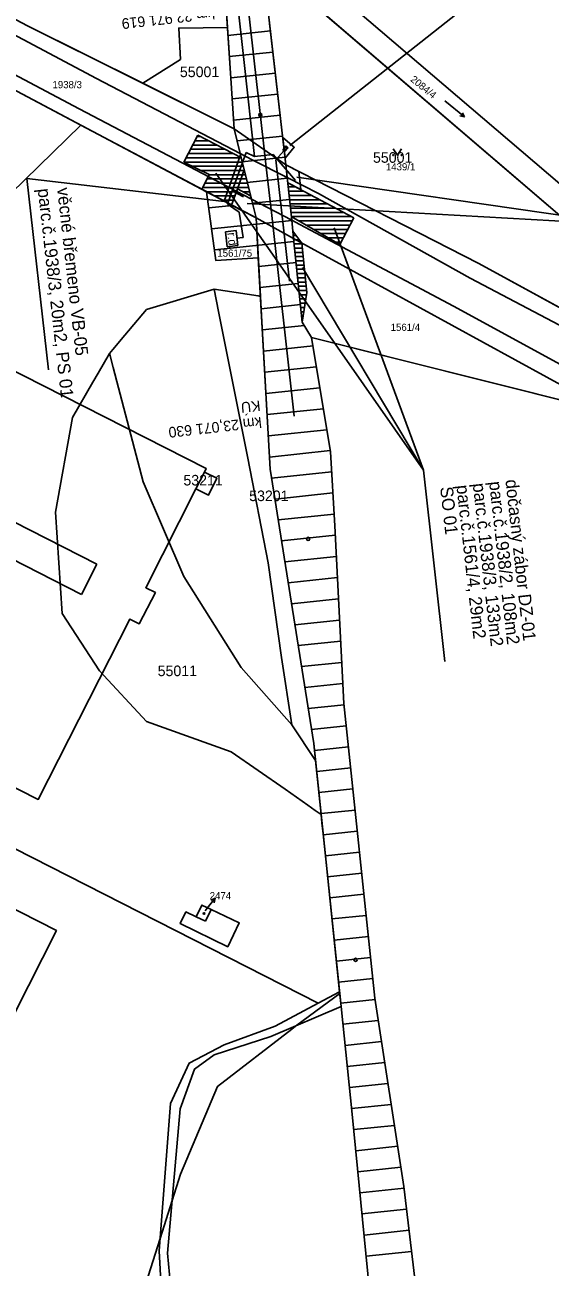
# Model space of a CAD drawing. Extents: x -794765 to -785424, y -1118958 to -1108731.
# Drawn here: x -792660.4 to -792536.3, y -1110737.1 to -1110443.9 of the extents above; entities that cross this region are included whole.
import ezdxf

# ---------------------------------------------------------------- set-up
doc = ezdxf.new("R2010")
doc.units = 0
for name, color, linetype in [('Level 66', 7, 'Continuous'), ('Level 75', 7, 'Continuous'), ('Level 76', 7, 'Continuous'), ('Level 77', 7, 'Continuous'), ('Level 78', 7, 'Continuous'), ('Level 79', 7, 'Continuous'), ('Level 80', 7, 'Continuous'), ('Level 81', 7, 'Continuous'), ('Vrstva 1', 7, 'Continuous'), ('Vrstva 53', 7, 'Continuous')]:
    doc.layers.add(name, color=color, linetype=linetype)

msp = doc.modelspace()

# ---------------------------------------------------------------- linework, layer by layer
at = {"layer": 'Level 66'}
for p, q in [((-792561.2, -1110461.83), (-792556.54, -1110465.6)), ((-792556.54, -1110465.6), (-792557.62, -1110465.38)), ((-792556.54, -1110465.6), (-792556.98, -1110464.6))]:
    msp.add_line(p, q, dxfattribs=at)
msp.add_lwpolyline([(-792573.4, -1110473.11), (-792572.4, -1110474.61), (-792571.4, -1110473.11)], dxfattribs=at)
for centre in [(-792573.4, -1110474.61), (-792571.4, -1110474.61)]:
    msp.add_circle(centre, 0.1, dxfattribs=at)
at = {"layer": 'Level 75'}
for p, q in [((-792605.76, -1110415.98), (-792598.74, -1110476.89)), ((-792609.51, -1110474.26), (-792610.94, -1110468.39)), ((-792606.89, -1110485.01), (-792609.51, -1110474.26)), ((-792598.74, -1110476.89), (-792598.42, -1110479.91)), ((-792598.42, -1110479.91), (-792597.37, -1110489.98)), ((-792617.47, -1110483.28), (-792605.8, -1110489.46)), ((-792605.8, -1110489.46), (-792606.89, -1110485.01)), ((-792605.8, -1110489.46), (-792605.27, -1110498.84)), ((-792605.8, -1110489.46), (-792596.92, -1110494.31)), ((-792597.37, -1110489.98), (-792596.92, -1110494.31)), ((-792521.65, -1110535.49), (-792596.92, -1110494.31)), ((-792592.65, -1110517.65), (-792521.65, -1110535.49)), ((-792717.66, -1110610.53), (-792591.1, -1110674.8)), ((-792586.07, -1110672.12), (-792591.1, -1110674.8)), ((-792585.71, -1110675.6), (-792586.07, -1110672.12))]:
    msp.add_line(p, q, dxfattribs=at)
for points in [[(-792861.96, -1110336.71), (-792834.85, -1110346.23), (-792831.02, -1110348.4), (-792787.15, -1110373.19), (-792780.58, -1110380.1), (-792659.8, -1110444.12), (-792610.94, -1110468.39)], [(-792606.36, -1110410.71), (-792601.62, -1110412.42), (-792591.51, -1110432.33), (-792497.5, -1110512.53), (-792447.39, -1110553.73)], [(-792610.94, -1110468.39), (-792611.85, -1110455.28), (-792614.37, -1110416.71), (-792614.4, -1110416.41)], [(-792451.16, -1110559.06), (-792501.08, -1110517.07), (-792597.68, -1110434.36), (-792604.19, -1110416.91), (-792605.76, -1110415.98)], [(-792617.47, -1110483.28), (-792667.41, -1110456.84), (-792670.27, -1110455.33)], [(-792598.74, -1110476.89), (-792553.17, -1110500.22), (-792498.93, -1110529.8)], [(-792605.27, -1110498.84), (-792615.26, -1110499.53), (-792617.47, -1110483.28)], [(-792596.92, -1110494.31), (-792594.86, -1110514.07), (-792592.65, -1110517.65)], [(-792605.27, -1110498.84), (-792602.43, -1110548.75), (-792592.15, -1110613.52), (-792589.48, -1110639.3), (-792589.16, -1110642.36), (-792586.07, -1110672.12)], [(-792721.79, -1110511.93), (-792715.49, -1110515.15), (-792708.94, -1110502.27), (-792617.55, -1110548.61), (-792617.98, -1110549.46), (-792615.07, -1110550.92), (-792617.03, -1110554.92), (-792619.99, -1110553.41), (-792631.85, -1110576.75), (-792629.58, -1110577.89), (-792633.4, -1110585.25), (-792635.6, -1110584.14), (-792657.23, -1110626.73), (-792748.62, -1110580.29), (-792742.08, -1110567.4), (-792748.36, -1110564.21)], [(-792592.65, -1110517.65), (-792588.22, -1110544.64), (-792587.19, -1110562.1), (-792585.02, -1110604.07), (-792577.72, -1110673.66), (-792570.87, -1110718.09), (-792561.36, -1110798.02), (-792555.3, -1110868.45), (-792554.86, -1110872.76)], [(-792692.14, -1110649.21), (-792691.69, -1110649.43), (-792687.06, -1110640.34), (-792652.95, -1110657.7), (-792692.66, -1110735.91), (-792726.8, -1110718.56), (-792722.01, -1110709.13)], [(-792619.91, -1110654.4), (-792618.59, -1110651.65), (-792616.4, -1110652.69), (-792609.75, -1110655.86), (-792612.47, -1110661.5), (-792623.69, -1110656.05), (-792622.34, -1110653.28), (-792619.91, -1110654.4)], [(-792591.1, -1110674.8), (-792601.29, -1110680.22), (-792613.33, -1110684.67), (-792621.59, -1110688.96), (-792626.04, -1110698.47), (-792628.69, -1110733.25), (-792627.76, -1110750.6), (-792629.75, -1110793.66), (-792632.7, -1110825.48)], [(-792585.71, -1110675.6), (-792602.33, -1110682.67), (-792615.66, -1110686.98), (-792620.3, -1110690.38), (-792623.71, -1110699.73), (-792626.72, -1110733.83), (-792625.08, -1110751.48), (-792626.88, -1110794.12), (-792629.4, -1110816.41), (-792632.7, -1110825.48)], [(-792564.11, -1110874.31), (-792564.67, -1110869.51), (-792573.72, -1110796.5), (-792583.08, -1110701.05), (-792585.71, -1110675.6)]]:
    msp.add_lwpolyline(points, dxfattribs=at)
at = {"layer": 'Level 77'}
for p, q in [((-792643.45, -1110456.57), (-792675.45, -1110439.61)), ((-792678.77, -1110447.22), (-792647.57, -1110463.72)), ((-792643.45, -1110456.57), (-792609.51, -1110474.26)), ((-792647.57, -1110463.72), (-792608.66, -1110484.08)), ((-792598.74, -1110476.89), (-792610.94, -1110468.39)), ((-792606.67, -1110475.74), (-792609.51, -1110474.26)), ((-792606.67, -1110475.74), (-792598.42, -1110479.91)), ((-792591.02, -1110483.65), (-792598.42, -1110479.91)), ((-792608.66, -1110484.08), (-792606.89, -1110485.01)), ((-792606.89, -1110485.01), (-792597.37, -1110489.98)), ((-792555.17, -1110503.69), (-792591.02, -1110483.65)), ((-792595.45, -1110490.98), (-792597.37, -1110489.98)), ((-792595.45, -1110490.98), (-792559.11, -1110510.27)), ((-792527.76, -1110518.12), (-792555.17, -1110503.69)), ((-792559.11, -1110510.27), (-792531.29, -1110525.47)), ((-792723.33, -1110530.62), (-792643.41, -1110571.15)), ((-792726.95, -1110537.73), (-792647.05, -1110578.32)), ((-792619.99, -1110553.41), (-792617.98, -1110549.46)), ((-792643.41, -1110571.15), (-792647.05, -1110578.32)), ((-792616.4, -1110652.69), (-792617.71, -1110655.45)), ((-792617.71, -1110655.45), (-792619.91, -1110654.4))]:
    msp.add_line(p, q, dxfattribs=at)
at = {"layer": 'Level 78'}
for p, q in [((-792612.43, -1110446.37), (-792602.38, -1110445.31)), ((-792612.11, -1110451.36), (-792601.81, -1110450.28)), ((-792611.78, -1110456.35), (-792601.23, -1110455.25)), ((-792611.43, -1110461.35), (-792600.66, -1110460.21)), ((-792611.08, -1110466.34), (-792600.09, -1110465.18)), ((-792610.24, -1110471.28), (-792599.52, -1110470.15)), ((-792609.04, -1110476.18), (-792598.94, -1110475.12)), ((-792607.85, -1110481.08), (-792598.41, -1110480.09)), ((-792606.65, -1110485.98), (-792597.88, -1110485.06)), ((-792616.96, -1110487.06), (-792611.42, -1110486.48)), ((-792616.28, -1110492.02), (-792597.36, -1110490.03)), ((-792615.61, -1110496.98), (-792596.85, -1110495.01)), ((-792605.15, -1110500.91), (-792596.33, -1110499.98)), ((-792604.86, -1110505.9), (-792595.81, -1110504.95)), ((-792604.58, -1110510.9), (-792595.29, -1110509.92)), ((-792604.29, -1110515.9), (-792594.37, -1110514.86)), ((-792604.01, -1110520.9), (-792592.32, -1110519.67)), ((-792603.73, -1110525.89), (-792591.51, -1110524.61)), ((-792603.44, -1110530.89), (-792590.7, -1110529.55)), ((-792603.16, -1110535.89), (-792589.89, -1110534.49)), ((-792602.88, -1110540.89), (-792589.07, -1110539.44)), ((-792602.59, -1110545.89), (-792588.26, -1110544.38)), ((-792602.1, -1110550.86), (-792587.94, -1110549.37)), ((-792601.31, -1110555.81), (-792587.65, -1110554.37)), ((-792600.53, -1110560.75), (-792587.35, -1110559.37)), ((-792599.74, -1110565.7), (-792587.07, -1110564.36)), ((-792598.96, -1110570.64), (-792586.81, -1110569.36)), ((-792598.17, -1110575.59), (-792586.56, -1110574.36)), ((-792597.39, -1110580.53), (-792586.3, -1110579.37)), ((-792596.6, -1110585.48), (-792586.04, -1110584.37)), ((-792595.82, -1110590.42), (-792585.78, -1110589.37)), ((-792595.03, -1110595.37), (-792585.52, -1110594.37)), ((-792594.25, -1110600.31), (-792585.26, -1110599.37)), ((-792593.46, -1110605.26), (-792584.99, -1110604.37)), ((-792592.68, -1110610.2), (-792584.47, -1110609.34)), ((-792591.98, -1110615.16), (-792583.95, -1110614.31)), ((-792591.46, -1110620.13), (-792583.42, -1110619.28)), ((-792590.95, -1110625.1), (-792582.9, -1110624.26)), ((-792590.43, -1110630.08), (-792582.38, -1110629.23)), ((-792589.92, -1110635.05), (-792581.86, -1110634.2)), ((-792589.4, -1110640.02), (-792581.34, -1110639.17)), ((-792588.88, -1110645), (-792580.82, -1110644.15)), ((-792588.37, -1110649.97), (-792580.29, -1110649.12)), ((-792587.85, -1110654.94), (-792579.77, -1110654.09)), ((-792587.34, -1110659.92), (-792579.25, -1110659.07)), ((-792586.82, -1110664.89), (-792578.73, -1110664.04)), ((-792586.31, -1110669.86), (-792578.21, -1110669.01)), ((-792585.79, -1110674.84), (-792577.67, -1110673.98)), ((-792585.28, -1110679.81), (-792576.91, -1110678.93)), ((-792584.76, -1110684.78), (-792576.14, -1110683.88)), ((-792584.25, -1110689.76), (-792575.38, -1110688.82)), ((-792583.73, -1110694.73), (-792574.62, -1110693.77)), ((-792583.22, -1110699.7), (-792573.86, -1110698.72)), ((-792582.72, -1110704.68), (-792573.09, -1110703.67)), ((-792582.24, -1110709.65), (-792572.33, -1110708.61)), ((-792581.75, -1110714.63), (-792571.57, -1110713.56)), ((-792581.26, -1110719.61), (-792570.82, -1110718.51)), ((-792580.77, -1110724.58), (-792570.23, -1110723.48)), ((-792580.28, -1110729.56), (-792569.64, -1110728.44)), ((-792579.8, -1110734.54), (-792569.05, -1110733.41))]:
    msp.add_line(p, q, dxfattribs=at)
at = {"layer": 'Level 79'}
msp.add_circle((-792618.08, -1110653.65), 0.175, dxfattribs=at)
at = {"layer": 'Level 80'}
for p, q in [((-792617.31, -1110652.36), (-792615.42, -1110650.03)), ((-792615.42, -1110650.03), (-792616.44, -1110650.49)), ((-792615.42, -1110650.03), (-792615.66, -1110651.12)), ((-792617.84, -1110653), (-792617.31, -1110652.36))]:
    msp.add_line(p, q, dxfattribs=at)
at = {"layer": 'Level 81'}
for p, q in [((-792593.91, -1110437.59), (-792502.91, -1110515.5)), ((-792674.7, -1110494.31), (-792647.2, -1110467.54)), ((-792597.35, -1110609.14), (-792591.73, -1110617.57)), ((-792591.73, -1110617.57), (-792590.41, -1110630.32))]:
    msp.add_line(p, q, dxfattribs=at)
for points in [[(-792739.95, -1110324.15), (-792684.9, -1110369.28), (-792666.12, -1110385.5), (-792634.65, -1110411.27), (-792624.78, -1110416.77), (-792614.4, -1110416.41), (-792614.37, -1110416.71), (-792612.56, -1110444.48)], [(-792733.14, -1110405.24), (-792659.8, -1110444.12), (-792632.57, -1110457.65)], [(-792744.86, -1110416.1), (-792741.07, -1110418.09), (-792681.03, -1110449.67), (-792667.41, -1110456.84), (-792647.2, -1110467.54)], [(-792632.57, -1110457.65), (-792623.67, -1110452.04), (-792624.04, -1110444.63), (-792612.56, -1110444.48)], [(-792632.57, -1110457.65), (-792610.94, -1110468.39), (-792611.85, -1110455.28), (-792612.56, -1110444.48)], [(-792602.59, -1110443.51), (-792598.74, -1110476.89), (-792553.17, -1110500.22), (-792510.76, -1110523.35)], [(-792647.2, -1110467.54), (-792605.8, -1110489.46), (-792604.74, -1110508.01)], [(-792640.41, -1110521.42), (-792639.64, -1110520.51), (-792636.77, -1110517.11), (-792631.64, -1110511.05), (-792615.69, -1110506.27)], [(-792615.69, -1110506.27), (-792605.32, -1110507.86), (-792604.74, -1110508.01)], [(-792615.69, -1110506.27), (-792614.64, -1110511.53), (-792607.72, -1110546.14), (-792602.93, -1110570.87), (-792599.74, -1110593.19), (-792597.35, -1110609.14)], [(-792604.74, -1110508.01), (-792604.4, -1110513.99), (-792602.43, -1110548.75), (-792592.15, -1110613.52), (-792591.73, -1110617.57)], [(-792561.36, -1110798.02), (-792570.87, -1110718.09), (-792577.72, -1110673.66), (-792585.02, -1110604.07), (-792587.19, -1110562.1), (-792588.22, -1110544.64), (-792592.65, -1110517.65), (-792521.65, -1110535.49), (-792507.87, -1110543.93), (-792480.76, -1110589.07), (-792470.5, -1110600.97), (-792465.27, -1110607.03), (-792463.97, -1110608.54), (-792457.87, -1110610.45), (-792459.97, -1110623.35), (-792464.15, -1110640.29), (-792461.3, -1110649.15), (-792444.03, -1110661.2), (-792443.21, -1110662.17)], [(-792640.41, -1110521.42), (-792643.13, -1110526.12), (-792644.35, -1110528.22), (-792649.18, -1110536.57), (-792653.17, -1110558.9), (-792651.58, -1110582.83), (-792642.81, -1110596.38), (-792631.64, -1110608.35), (-792611.7, -1110615.52), (-792598.94, -1110624.3), (-792593.55, -1110628.1), (-792591.81, -1110629.33), (-792590.41, -1110630.32)], [(-792640.41, -1110521.42), (-792640.35, -1110521.65), (-792639.53, -1110524.79), (-792632.44, -1110551.73), (-792622.87, -1110574.06), (-792609.31, -1110595.59), (-792597.35, -1110609.14)], [(-792590.41, -1110630.32), (-792590.21, -1110632.23), (-792589.94, -1110634.82), (-792589.48, -1110639.3), (-792589.16, -1110642.36), (-792586.07, -1110672.12), (-792586.02, -1110672.57)], [(-792649.15, -1110846.82), (-792642.01, -1110836.43), (-792638.82, -1110814.1), (-792636.43, -1110779.01), (-792634.03, -1110747.91), (-792628.47, -1110730.36), (-792625.62, -1110721.38), (-792623.67, -1110715.21), (-792614.89, -1110694.48), (-792597.35, -1110680.92), (-792596.17, -1110680.05), (-792586.02, -1110672.57)], [(-792586.02, -1110672.57), (-792585.71, -1110675.6), (-792583.08, -1110701.05), (-792573.72, -1110796.5), (-792564.67, -1110869.51), (-792564.11, -1110874.31), (-792552.78, -1110972.03), (-792550.9, -1110987.8), (-792549.9, -1110996.2), (-792549.58, -1110998.89), (-792549, -1111003.82), (-792541.78, -1111065.45)]]:
    msp.add_lwpolyline(points, dxfattribs=at)
at = {"layer": 'Vrstva 1'}
for p, q in [((-792613.96, -1110405.45), (-792608.61, -1110452.76)), ((-792608.61, -1110452.76), (-792606.17, -1110474.95)), ((-792619.53, -1110469.94), (-792622.88, -1110476.25)), ((-792620.23, -1110471.25), (-792617, -1110471.25)), ((-792619.7, -1110470.25), (-792618.92, -1110470.25)), ((-792619.53, -1110469.94), (-792609.26, -1110475.29)), ((-792596.78, -1110472.75), (-792599.48, -1110470.49)), ((-792621.82, -1110474.25), (-792611.25, -1110474.25)), ((-792621.29, -1110473.25), (-792613.17, -1110473.25)), ((-792620.76, -1110472.25), (-792615.09, -1110472.25)), ((-792609.44, -1110474.53), (-792613.35, -1110485.46)), ((-792608.13, -1110474.01), (-792611.42, -1110483.05)), ((-792606.17, -1110474.95), (-792608.13, -1110474.01)), ((-792606.17, -1110474.95), (-792601.71, -1110474.49)), ((-792601.71, -1110474.49), (-792596.44, -1110480.58)), ((-792601.15, -1110475.7), (-792599.22, -1110473.58)), ((-792598.7, -1110472.45), (-792599.47, -1110473.37)), ((-792598.7, -1110472.45), (-792599.47, -1110473.37)), ((-792599.47, -1110473.37), (-792598.96, -1110473.79)), ((-792599.47, -1110473.37), (-792598.96, -1110473.79)), ((-792599.29, -1110472.15), (-792599.29, -1110472.15)), ((-792598.58, -1110472.54), (-792599.22, -1110473.31)), ((-792598.58, -1110472.54), (-792599.22, -1110473.31)), ((-792599.22, -1110473.31), (-792598.95, -1110473.54)), ((-792599.22, -1110473.31), (-792598.95, -1110473.54)), ((-792598.96, -1110473.79), (-792598.19, -1110472.87)), ((-792598.19, -1110472.87), (-792598.96, -1110473.79)), ((-792598.95, -1110473.54), (-792598.31, -1110472.78)), ((-792598.31, -1110472.78), (-792598.95, -1110473.54)), ((-792598.92, -1110475.3), (-792596.78, -1110472.75)), ((-792598.19, -1110472.87), (-792598.7, -1110472.45)), ((-792598.19, -1110472.87), (-792598.7, -1110472.45)), ((-792622.88, -1110476.25), (-792616.88, -1110479.22)), ((-792622.88, -1110476.25), (-792609.03, -1110476.25)), ((-792622.35, -1110475.25), (-792609.33, -1110475.25)), ((-792620.86, -1110477.25), (-792608.78, -1110477.25)), ((-792597.92, -1110504.39), (-792601.15, -1110475.7)), ((-792598.74, -1110476.89), (-792598.42, -1110479.91)), ((-792654.86, -1110525.34), (-792659.91, -1110480.13)), ((-792659.91, -1110480.13), (-792612.63, -1110485.66)), ((-792618.84, -1110478.25), (-792608.54, -1110478.25)), ((-792618.57, -1110482.7), (-792616.88, -1110479.22)), ((-792617.39, -1110480.25), (-792608.05, -1110480.25)), ((-792616.9, -1110479.25), (-792608.3, -1110479.25)), ((-792566.22, -1110549), (-792615.31, -1110478.87)), ((-792608.58, -1110478.06), (-792610.18, -1110482.54)), ((-792518.1, -1110491.09), (-792596.16, -1110479.83)), ((-792618.36, -1110482.25), (-792607.57, -1110482.25)), ((-792617.87, -1110481.25), (-792607.81, -1110481.25)), ((-792617.52, -1110483.25), (-792610.43, -1110483.25)), ((-792617.47, -1110483.28), (-792617.47, -1110483.28)), ((-792611.42, -1110483.05), (-792612.54, -1110486.17)), ((-792610.18, -1110482.54), (-792611.56, -1110486.41)), ((-792611.42, -1110483.05), (-792608.74, -1110484.47)), ((-792607.08, -1110484.25), (-792610.18, -1110482.54)), ((-792610.18, -1110482.54), (-792610.18, -1110482.54)), ((-792608.89, -1110483.25), (-792607.32, -1110483.25)), ((-792598.29, -1110481.14), (-792582.67, -1110489.42)), ((-792598.19, -1110482.14), (-792596.4, -1110482.14)), ((-792598.08, -1110483.14), (-792594.51, -1110483.14)), ((-792615.63, -1110484.25), (-792610.79, -1110484.25)), ((-792613.75, -1110485.25), (-792611.15, -1110485.25)), ((-792612.54, -1110486.17), (-792609.77, -1110488.09)), ((-792611.86, -1110486.25), (-792611.5, -1110486.25)), ((-792607.87, -1110486.02), (-792518.1, -1110491.09)), ((-792605.8, -1110489.46), (-792606.89, -1110485.01)), ((-792597.98, -1110484.14), (-792592.63, -1110484.14)), ((-792597.87, -1110485.14), (-792590.75, -1110485.14)), ((-792597.77, -1110486.14), (-792588.86, -1110486.14)), ((-792609.77, -1110488.09), (-792608.83, -1110494.04)), ((-792597.67, -1110487.14), (-792586.98, -1110487.14)), ((-792597.56, -1110488.14), (-792585.09, -1110488.14)), ((-792585.96, -1110495.68), (-792597.46, -1110489.11)), ((-792597.42, -1110489.14), (-792583.21, -1110489.14)), ((-792595.67, -1110490.14), (-792583.04, -1110490.14)), ((-792593.92, -1110491.14), (-792583.57, -1110491.14)), ((-792592.17, -1110492.14), (-792584.1, -1110492.14)), ((-792566.22, -1110549), (-792587.31, -1110491.82)), ((-792582.67, -1110489.42), (-792585.96, -1110495.68)), ((-792610.51, -1110492.41), (-792612.99, -1110492.7)), ((-792612.99, -1110492.7), (-792612.58, -1110496.28)), ((-792610.09, -1110495.99), (-792610.51, -1110492.41)), ((-792608.83, -1110494.04), (-792610.3, -1110494.2)), ((-792594.95, -1110495.44), (-792597.1, -1110492.58)), ((-792597, -1110493.58), (-792596.35, -1110493.58)), ((-792596.89, -1110494.58), (-792595.6, -1110494.58)), ((-792590.42, -1110493.14), (-792584.62, -1110493.14)), ((-792588.66, -1110494.14), (-792585.15, -1110494.14)), ((-792612.58, -1110496.28), (-792610.09, -1110495.99)), ((-792596.79, -1110495.58), (-792594.94, -1110495.58)), ((-792596.68, -1110496.58), (-792594.84, -1110496.58)), ((-792596.58, -1110497.58), (-792594.73, -1110497.58)), ((-792593.77, -1110507.02), (-792594.95, -1110495.44)), ((-792586.91, -1110495.14), (-792585.67, -1110495.14)), ((-792596.47, -1110498.58), (-792594.63, -1110498.58)), ((-792596.37, -1110499.58), (-792594.53, -1110499.58)), ((-792596.27, -1110500.58), (-792594.43, -1110500.58)), ((-792596.16, -1110501.58), (-792594.33, -1110501.58)), ((-792596.06, -1110502.58), (-792594.22, -1110502.58)), ((-792595.95, -1110503.58), (-792594.12, -1110503.58)), ((-792566.22, -1110549), (-792594.81, -1110501.17)), ((-792595.85, -1110504.58), (-792594.02, -1110504.58)), ((-792595.74, -1110505.58), (-792593.92, -1110505.58)), ((-792595.64, -1110506.58), (-792593.82, -1110506.58)), ((-792595.54, -1110507.58), (-792593.86, -1110507.58)), ((-792595.43, -1110508.58), (-792594.01, -1110508.58)), ((-792595.33, -1110509.58), (-792594.17, -1110509.58)), ((-792594.86, -1110514.07), (-792593.77, -1110507.02)), ((-792595.22, -1110510.58), (-792594.32, -1110510.58)), ((-792595.12, -1110511.58), (-792594.48, -1110511.58)), ((-792595.01, -1110512.58), (-792594.63, -1110512.58)), ((-792594.91, -1110513.58), (-792594.79, -1110513.58)), ((-792561.17, -1110594.2), (-792566.22, -1110549))]:
    msp.add_line(p, q, dxfattribs=at)
for points in [[(-792607.94, -1110436.89), (-792605.57, -1110457.95), (-792605.12, -1110461.93), (-792603.37, -1110477.43), (-792602.17, -1110488.16), (-792596.75, -1110536.28)], [(-792597.8, -1110472.33), (-792556.76, -1110440)]]:
    msp.add_lwpolyline(points, dxfattribs=at)
for points in [[(-792599.48, -1110470.49), (-792596.78, -1110472.75), (-792598.92, -1110475.3)], [(-792609.44, -1110474.53), (-792613.35, -1110485.46), (-792611.56, -1110486.41), (-792610.18, -1110482.54), (-792608.58, -1110478.06)], [(-792598.74, -1110476.89), (-792595.67, -1110478.46), (-792595.21, -1110482.77), (-792598.29, -1110481.14), (-792598.42, -1110479.91)], [(-792610.18, -1110482.54), (-792607.08, -1110484.25), (-792606.89, -1110485.01), (-792605.8, -1110489.46), (-792611.56, -1110486.41)]]:
    msp.add_lwpolyline(points, close=True, dxfattribs=at)
for centre in [(-792604.77, -1110465.1), (-792593.47, -1110565.22), (-792582.28, -1110664.59)]:
    msp.add_circle(centre, 0.375, dxfattribs=at)
at = {"layer": 'Vrstva 53'}
for points in [[(-792611.85, -1110455.28), (-792614.4, -1110416.41), (-792614.4, -1110416.41), (-792612.51, -1110416.31), (-792612.65, -1110414.98), (-792608.39, -1110414.49), (-792608.23, -1110416.1), (-792605.76, -1110415.98), (-792598.74, -1110476.89)], [(-792573.72, -1110796.5), (-792583.08, -1110701.05), (-792585.71, -1110675.6), (-792592.15, -1110613.52), (-792602.43, -1110548.75), (-792604.4, -1110513.99), (-792605.27, -1110498.84), (-792615.26, -1110499.53), (-792617.47, -1110483.28), (-792605.8, -1110489.46), (-792606.89, -1110485.01), (-792609.51, -1110474.26), (-792610.94, -1110468.39), (-792611.85, -1110455.28)], [(-792598.74, -1110476.89), (-792597.37, -1110489.98), (-792596.92, -1110494.31), (-792594.86, -1110514.07), (-792592.65, -1110517.65), (-792588.22, -1110544.64), (-792587.19, -1110562.1), (-792585.02, -1110604.07), (-792577.72, -1110673.66), (-792570.87, -1110718.09), (-792561.36, -1110798.02)]]:
    msp.add_lwpolyline(points, dxfattribs=at)

# ---------------------------------------------------------------- texts
at = {"layer": 'Level 76'}
msp.add_text('2084/4', height=1.7, rotation=321, dxfattribs=at).set_placement((-792569.46, -1110457.01))
for s, p in [('1938/3', (-792653.88, -1110458.83)), ('1439/1', (-792575.11, -1110478.22)), ('1561/75', (-792614.93, -1110498.6)), ('1561/4', (-792573.98, -1110516.11)), ('2474', (-792616.74, -1110650.31))]:
    msp.add_text(s, height=1.7, dxfattribs=at).set_placement(p)
at = {"layer": 'Level 81'}
for s, p in [('55001', (-792623.78, -1110456.21)), ('55001', (-792578.16, -1110476.43)), ('53211', (-792622.95, -1110552.61)), ('53201', (-792607.41, -1110556.3)), ('55011', (-792629.03, -1110597.62))]:
    msp.add_text(s, height=2.5, dxfattribs=at).set_placement(p)
at = {"layer": 'Vrstva 1'}
for s, height, rotation, p in [('km 22,971 619', 2.5, 186.4259, (-792615.67, -1110439.93)), ('parc.č.1938/3, 20m2, PS 01', 3, 276.3763, (-792657.38, -1110482.62)), ('věcné břemeno VB-05', 3, 276.3763, (-792652.81, -1110482.43)), ('r.d.', 2, 276.5388, (-792612.6, -1110492.98)), ('KÚ', 2.5, 186.0649, (-792604.88, -1110532.52)), ('km 23,071 630', 2.5, 186.4259, (-792604.61, -1110536.4)), ('SO 01', 3, 276.3763, (-792562.31, -1110553.05)), ('parc.č.1561/4, 29m2', 3, 276.3763, (-792558.46, -1110552.62)), ('parc.č.1938/3, 133m2', 3, 276.3763, (-792554.6, -1110552.19)), ('parc.č.1938/2, 108m2', 3, 276.3763, (-792550.74, -1110551.76)), ('dočasný zábor DZ-01', 3, 276.3763, (-792546.88, -1110551.33))]:
    msp.add_text(s, height=height, rotation=rotation, dxfattribs=at).set_placement(p)

doc.saveas('drawing.dxf')
